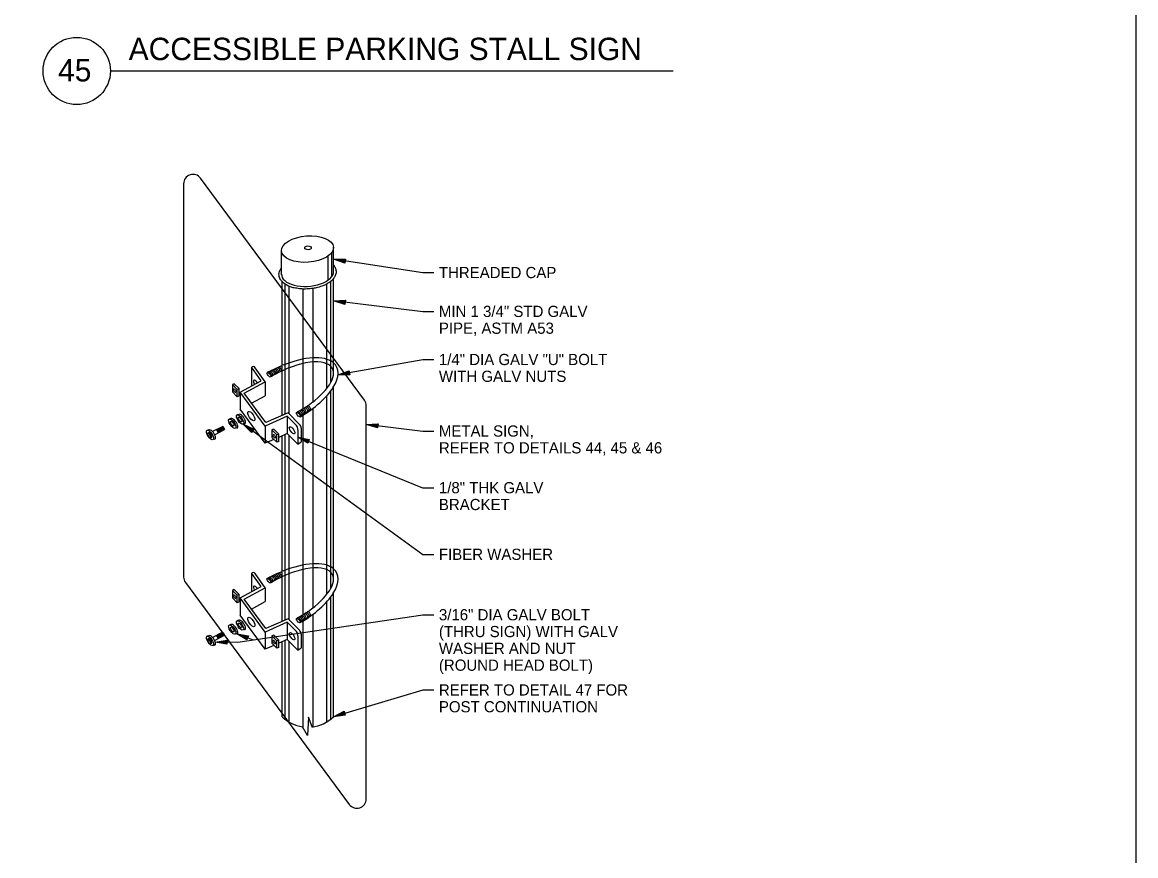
# Model space of a CAD drawing. Extents: x -121933 to -117742, y -103160 to -100084.
# Drawn here: x -118338 to -117742, y -102023 to -101577 of the extents above; entities that cross this region are included whole.
import ezdxf

# ---------------------------------------------------------------- set-up
doc = ezdxf.new("R2010")
doc.units = 0
for name, color, linetype in [('22', 7, 'Continuous'), ('Default', 7, 'Continuous'), ('Misc CnstDet(22)', 7, 'Continuous')]:
    doc.layers.add(name, color=color, linetype=linetype)

msp = doc.modelspace()

# ---------------------------------------------------------------- linework, layer by layer
at = {"layer": '22'}
for p, q in [((-118155.15, -101778.96), (-118242.85, -101660.14)), ((-118251.87, -101663.11), (-118251.87, -101873.69)), ((-118199.46, -101712), (-118199.46, -101699.13)), ((-118174.47, -101714.69), (-118174.47, -101701.82)), ((-118172.49, -101712.73), (-118172.49, -101699.86)), ((-118171.67, -101710.02), (-118171.67, -101697.15)), ((-118171.67, -101764.89), (-118171.67, -101713.91)), ((-118199.06, -101787.14), (-118199.06, -101715.7)), ((-118197.58, -101786.48), (-118197.58, -101716.9)), ((-118195.43, -101786.35), (-118195.43, -101718.01)), ((-118187.84, -101783.21), (-118187.84, -101719.48)), ((-118182.56, -101779.84), (-118182.56, -101719.15)), ((-118175.3, -101772.81), (-118175.3, -101716.82)), ((-118173.15, -101769.59), (-118173.15, -101715.4)), ((-118215.55, -101761.57), (-118215.55, -101771.42)), ((-118208.2, -101769.16), (-118213.52, -101761.62)), ((-118203.53, -101762.51), (-118207.22, -101764.25)), ((-118224.78, -101770.2), (-118225.76, -101770.62)), ((-118223.13, -101773.25), (-118225.76, -101770.62)), ((-118225.76, -101770.62), (-118225.76, -101774.52)), ((-118222.14, -101772.83), (-118224.78, -101770.2)), ((-118222.14, -101772.83), (-118223.13, -101773.25)), ((-118223.13, -101777.21), (-118223.13, -101773.25)), ((-118222.14, -101776.78), (-118222.14, -101772.83)), ((-118219.5, -101775.23), (-118208.2, -101769.16)), ((-118208.2, -101769.16), (-118208.2, -101776.64)), ((-118173.15, -101879.94), (-118173.15, -101774.11)), ((-118171.67, -101873.59), (-118171.67, -101771.91)), ((-118225.76, -101774.57), (-118223.13, -101777.21)), ((-118222.14, -101776.78), (-118223.13, -101777.21)), ((-118221.62, -101774.66), (-118221.62, -101783.89)), ((-118207.82, -101791.05), (-118219.5, -101775.23)), ((-118175.3, -101883.05), (-118175.3, -101776.72)), ((-118196, -101785.78), (-118207.82, -101791.05)), ((-118189.79, -101791.99), (-118196, -101785.78)), ((-118182.56, -101889.82), (-118182.56, -101783.71)), ((-118154.17, -101992.5), (-118154.17, -101781.93)), ((-118226.52, -101788.88), (-118227.56, -101789.17)), ((-118222.33, -101786.62), (-118223.37, -101786.91)), ((-118218.94, -101791.52), (-118219.98, -101791.81)), ((-118196.48, -101787.66), (-118196.48, -101796.89)), ((-118187.84, -101893.81), (-118187.84, -101787.34)), ((-118238.39, -101794.92), (-118239.42, -101795.2)), ((-118238.91, -101796.66), (-118238.43, -101796.38)), ((-118238.15, -101797.08), (-118237.68, -101796.8)), ((-118237.35, -101798.26), (-118236.88, -101797.97)), ((-118231.28, -101793.22), (-118236.41, -101795.76)), ((-118230.24, -101794.83), (-118235.23, -101797.51)), ((-118232.97, -101796.28), (-118234.29, -101794.68)), ((-118234.29, -101794.68), (-118233.3, -101796.47)), ((-118232.69, -101796.14), (-118233.96, -101794.54)), ((-118233.96, -101794.54), (-118232.97, -101796.28)), ((-118232.36, -101795.95), (-118233.58, -101794.35)), ((-118233.58, -101794.35), (-118232.69, -101796.14)), ((-118232.03, -101795.81), (-118233.26, -101794.26)), ((-118233.26, -101794.26), (-118232.36, -101795.95)), ((-118231.75, -101795.62), (-118232.97, -101794.12)), ((-118232.97, -101794.12), (-118232.03, -101795.81)), ((-118231.42, -101795.43), (-118232.74, -101793.98)), ((-118232.74, -101793.98), (-118231.75, -101795.62)), ((-118231.04, -101795.25), (-118232.41, -101793.79)), ((-118232.41, -101793.79), (-118231.42, -101795.43)), ((-118230.66, -101795.06), (-118232.03, -101793.64)), ((-118232.03, -101793.64), (-118231.04, -101795.25)), ((-118230.33, -101794.92), (-118231.7, -101793.5)), ((-118231.7, -101793.5), (-118230.66, -101795.06)), ((-118230.05, -101794.68), (-118231.42, -101793.31)), ((-118231.42, -101793.31), (-118230.33, -101794.92)), ((-118230.05, -101794.3), (-118231.14, -101793.13)), ((-118231.14, -101793.13), (-118230.05, -101794.68)), ((-118230, -101794.3), (-118230.66, -101793.27)), ((-118223.13, -101793.79), (-118224.17, -101794.07)), ((-118208.15, -101792.89), (-118208.15, -101802.12)), ((-118203.64, -101794.54), (-118204.63, -101794.97)), ((-118201.98, -101797.6), (-118204.63, -101794.97)), ((-118204.63, -101794.97), (-118204.63, -101798.87)), ((-118200.99, -101797.18), (-118203.64, -101794.54)), ((-118200.99, -101797.18), (-118201.98, -101797.6)), ((-118201.98, -101801.55), (-118201.98, -101797.6)), ((-118200.99, -101801.13), (-118200.99, -101797.18)), ((-118199.06, -101897.33), (-118199.06, -101798)), ((-118197.58, -101896.72), (-118197.58, -101797.59)), ((-118195.43, -101896.59), (-118195.43, -101797.88)), ((-118190.83, -101794.97), (-118190.83, -101802.54)), ((-118189.03, -101793.98), (-118189.03, -101801.32)), ((-118237.3, -101799.11), (-118236.84, -101798.83)), ((-118234.99, -101799.82), (-118236.03, -101800.1)), ((-118204.63, -101798.92), (-118201.98, -101801.55)), ((-118200.99, -101801.13), (-118201.98, -101801.55)), ((-118190.83, -101802.54), (-118189.03, -101801.32)), ((-118215.55, -101871.81), (-118215.55, -101881.66)), ((-118208.2, -101879.4), (-118213.52, -101871.86)), ((-118203.53, -101872.75), (-118207.22, -101874.49)), ((-118250.89, -101876.66), (-118163.2, -101995.47)), ((-118224.78, -101880.44), (-118225.76, -101880.86)), ((-118223.13, -101883.49), (-118225.76, -101880.86)), ((-118225.76, -101880.86), (-118225.76, -101884.76)), ((-118222.14, -101883.07), (-118224.78, -101880.44)), ((-118219.5, -101885.47), (-118208.2, -101879.4)), ((-118208.2, -101879.4), (-118208.2, -101886.88)), ((-118225.76, -101884.81), (-118223.13, -101887.44)), ((-118222.14, -101883.07), (-118223.13, -101883.49)), ((-118223.13, -101887.44), (-118223.13, -101883.49)), ((-118222.14, -101887.02), (-118223.13, -101887.44)), ((-118222.14, -101887.02), (-118222.14, -101883.07)), ((-118221.62, -101884.9), (-118221.62, -101894.13)), ((-118207.82, -101901.29), (-118219.5, -101885.47)), ((-118175.3, -101951.31), (-118175.3, -101886.96)), ((-118173.15, -101949.81), (-118173.15, -101884.35)), ((-118171.67, -101948.49), (-118171.67, -101882.15)), ((-118226.52, -101899.12), (-118227.56, -101899.41)), ((-118222.33, -101896.86), (-118223.37, -101897.15)), ((-118196, -101896.02), (-118207.82, -101901.29)), ((-118196.48, -101897.9), (-118196.48, -101907.13)), ((-118189.79, -101902.23), (-118196, -101896.02)), ((-118187.84, -101954.62), (-118187.84, -101897.08)), ((-118182.56, -101953.9), (-118182.56, -101893.53)), ((-118238.39, -101905.16), (-118239.42, -101905.44)), ((-118231.28, -101903.46), (-118236.41, -101906)), ((-118230.24, -101905.07), (-118235.23, -101907.75)), ((-118232.97, -101906.52), (-118234.29, -101904.92)), ((-118234.29, -101904.92), (-118233.3, -101906.71)), ((-118232.69, -101906.38), (-118233.96, -101904.78)), ((-118233.96, -101904.78), (-118232.97, -101906.52)), ((-118232.36, -101906.19), (-118233.58, -101904.59)), ((-118233.58, -101904.59), (-118232.69, -101906.38)), ((-118232.03, -101906.05), (-118233.26, -101904.5)), ((-118233.26, -101904.5), (-118232.36, -101906.19)), ((-118231.75, -101905.86), (-118232.97, -101904.36)), ((-118232.97, -101904.36), (-118232.03, -101906.05)), ((-118231.42, -101905.67), (-118232.74, -101904.22)), ((-118232.74, -101904.22), (-118231.75, -101905.86)), ((-118231.04, -101905.49), (-118232.41, -101904.03)), ((-118232.41, -101904.03), (-118231.42, -101905.67)), ((-118230.66, -101905.3), (-118232.03, -101903.88)), ((-118232.03, -101903.88), (-118231.04, -101905.49)), ((-118230.33, -101905.16), (-118231.7, -101903.74)), ((-118231.7, -101903.74), (-118230.66, -101905.3)), ((-118230.05, -101904.92), (-118231.42, -101903.55)), ((-118231.42, -101903.55), (-118230.33, -101905.16)), ((-118230.05, -101904.54), (-118231.14, -101903.37)), ((-118231.14, -101903.37), (-118230.05, -101904.92)), ((-118230, -101904.54), (-118230.66, -101903.51)), ((-118223.13, -101904.03), (-118224.17, -101904.31)), ((-118218.94, -101901.76), (-118219.98, -101902.05)), ((-118208.15, -101903.13), (-118208.15, -101912.36)), ((-118203.64, -101904.78), (-118204.63, -101905.21)), ((-118201.98, -101907.84), (-118204.63, -101905.21)), ((-118204.63, -101905.21), (-118204.63, -101909.11)), ((-118200.99, -101907.42), (-118203.64, -101904.78)), ((-118190.83, -101905.21), (-118190.83, -101912.78)), ((-118189.03, -101904.22), (-118189.03, -101911.56)), ((-118238.91, -101906.9), (-118238.43, -101906.62)), ((-118238.15, -101907.32), (-118237.68, -101907.04)), ((-118237.35, -101908.5), (-118236.88, -101908.21)), ((-118237.3, -101909.35), (-118236.84, -101909.07)), ((-118234.99, -101910.06), (-118236.03, -101910.34)), ((-118204.63, -101909.16), (-118201.98, -101911.79)), ((-118200.99, -101907.42), (-118201.98, -101907.84)), ((-118201.98, -101911.79), (-118201.98, -101907.84)), ((-118200.99, -101911.37), (-118201.98, -101911.79)), ((-118200.99, -101911.37), (-118200.99, -101907.42)), ((-118199.06, -101948.49), (-118199.06, -101908.29)), ((-118197.58, -101949.81), (-118197.58, -101907.63)), ((-118195.43, -101951.31), (-118195.43, -101908.18)), ((-118190.83, -101912.78), (-118189.03, -101911.56)), ((-118185.1, -101948.65), (-118185.6, -101958.56)), ((-118183.14, -101953.98), (-118185.1, -101948.65)), ((-118185.6, -101958.56), (-118188.26, -101953.89))]:
    msp.add_line(p, q, dxfattribs=at)
for points in [[(-118165.32, -101703.45), (-118165.66, -101705.62), (-118171.67, -101703.58), (-118165.32, -101703.45), (-118165.78, -101704.49), (-118165.81, -101705.29), (-118170.32, -101703.74), (-118165.55, -101703.61), (-118165.98, -101704.46), (-118166.06, -101704.95), (-118169.19, -101703.91), (-118165.99, -101703.85), (-118166.18, -101704.78), (-118168.06, -101704.14), (-118166.23, -101704.12), (-118166.45, -101704.54), (-118167.07, -101704.29), (-118165.49, -101704.53)], [(-118117.93, -101710.9), (-118123.93, -101710.9), (-118171.67, -101703.58)], [(-118165.33, -101725.56), (-118165.59, -101727.75), (-118171.67, -101725.9), (-118165.33, -101725.56), (-118165.76, -101726.62), (-118165.76, -101727.43), (-118170.32, -101726.02), (-118165.55, -101725.74), (-118165.96, -101726.6), (-118166.02, -101727.09), (-118169.18, -101726.15), (-118165.98, -101725.99), (-118166.15, -101726.93), (-118168.04, -101726.34), (-118166.22, -101726.26), (-118166.42, -101726.69), (-118167.05, -101726.46), (-118165.46, -101726.66)], [(-118117.93, -101731.69), (-118123.93, -101731.69), (-118171.67, -101725.9)], [(-118191.53, -101792.61), (-118196.48, -101787.66), (-118208.15, -101792.89), (-118221.62, -101774.66), (-118210.32, -101768.59), (-118215.31, -101761.57)], [(-118117.93, -101757.44), (-118123.93, -101757.44), (-118169.26, -101765.52)], [(-118163.29, -101763.35), (-118162.91, -101765.52), (-118169.26, -101765.52), (-118163.29, -101763.35), (-118163.4, -101764.48), (-118163.16, -101765.26), (-118167.94, -101765.23), (-118163.46, -101763.58), (-118163.6, -101764.52), (-118163.51, -101765.01), (-118166.81, -101765.03), (-118163.8, -101763.95), (-118163.68, -101764.89), (-118165.66, -101764.88), (-118163.94, -101764.28), (-118164.01, -101764.75), (-118164.68, -101764.71), (-118163.1, -101764.43)], [(-118215.5, -101780.65), (-118208.2, -101776.64)], [(-118203.53, -101800.05), (-118208.15, -101802.12), (-118221.62, -101783.89)], [(-118117.93, -101861.74), (-118123.93, -101861.74), (-118219.98, -101791.81)], [(-118214.27, -101794.58), (-118215.56, -101796.36), (-118219.98, -101791.81), (-118214.27, -101794.58), (-118215.16, -101795.29), (-118215.55, -101796), (-118218.86, -101792.56), (-118214.55, -101794.62), (-118215.32, -101795.17), (-118215.62, -101795.58), (-118217.93, -101793.23), (-118215.05, -101794.63), (-118215.65, -101795.37), (-118217.03, -101793.94), (-118215.39, -101794.76), (-118215.78, -101795.03), (-118216.22, -101794.53), (-118214.92, -101795.47)], [(-118147.84, -101791.72), (-118148.1, -101793.9), (-118154.17, -101792.06), (-118147.84, -101791.72), (-118148.26, -101792.77), (-118148.26, -101793.58), (-118152.83, -101792.17), (-118148.06, -101791.89), (-118148.46, -101792.75), (-118148.52, -101793.25), (-118151.68, -101792.31), (-118148.49, -101792.14), (-118148.65, -101793.08), (-118150.55, -101792.5), (-118148.73, -101792.42), (-118148.93, -101792.84), (-118149.56, -101792.62), (-118147.97, -101792.81)], [(-118117.93, -101795.73), (-118123.93, -101795.73), (-118154.17, -101792.06)], [(-118237.59, -101797.83), (-118238.15, -101797.08), (-118238.91, -101796.66), (-118239.19, -101797.12), (-118238.81, -101798.02), (-118238.34, -101798.64), (-118237.83, -101799.11), (-118237.3, -101799.11), (-118237.35, -101798.26), (-118237.63, -101797.79)], [(-118237.12, -101797.55), (-118237.68, -101796.8), (-118238.43, -101796.38), (-118238.43, -101796.42)], [(-118236.88, -101798.83), (-118236.84, -101798.83), (-118236.88, -101797.97), (-118237.16, -101797.51)], [(-118190.83, -101802.54), (-118196.48, -101796.89), (-118200.99, -101798.92)], [(-118117.93, -101826.09), (-118123.93, -101826.09), (-118190.83, -101798.75)], [(-118184.62, -101800.08), (-118185.44, -101802.12), (-118190.83, -101798.75), (-118184.62, -101800.08), (-118185.31, -101800.98), (-118185.52, -101801.76), (-118189.56, -101799.21), (-118184.88, -101800.19), (-118185.5, -101800.91), (-118185.68, -101801.37), (-118188.49, -101799.64), (-118185.36, -101800.32), (-118185.77, -101801.18), (-118187.44, -101800.12), (-118185.66, -101800.52), (-118185.97, -101800.88), (-118186.52, -101800.5), (-118185.03, -101801.1)], [(-118191.53, -101902.85), (-118196.48, -101897.9), (-118208.15, -101903.13), (-118221.62, -101884.9), (-118210.32, -101878.83), (-118215.31, -101871.81)], [(-118215.5, -101890.89), (-118208.2, -101886.88)], [(-118117.93, -101894.09), (-118123.93, -101894.09), (-118222.94, -101908.66)], [(-118203.53, -101910.29), (-118208.15, -101912.36), (-118221.62, -101894.13)], [(-118214.56, -101907.42), (-118223.44, -101904.11)], [(-118217.2, -101905.24), (-118217.96, -101907.31), (-118223.44, -101904.11), (-118217.2, -101905.24), (-118217.86, -101906.17), (-118218.04, -101906.96), (-118222.16, -101904.53), (-118217.45, -101905.36), (-118218.04, -101906.1), (-118218.22, -101906.57), (-118221.08, -101904.93), (-118217.93, -101905.5), (-118218.31, -101906.38), (-118220.01, -101905.38), (-118218.22, -101905.72), (-118218.52, -101906.09), (-118219.08, -101905.72), (-118217.58, -101906.27)], [(-118237.59, -101908.07), (-118238.15, -101907.32), (-118238.91, -101906.9), (-118239.19, -101907.36), (-118238.81, -101908.26), (-118238.34, -101908.88), (-118237.83, -101909.35), (-118237.3, -101909.35), (-118237.35, -101908.5), (-118237.63, -101908.03)], [(-118237.12, -101907.79), (-118237.68, -101907.04), (-118238.43, -101906.62), (-118238.43, -101906.66)], [(-118236.88, -101909.07), (-118236.84, -101909.07), (-118236.88, -101908.21), (-118237.16, -101907.75)], [(-118228.64, -101907.48), (-118228.66, -101909.68), (-118234.9, -101908.52), (-118228.64, -101907.48), (-118228.95, -101908.58), (-118228.86, -101909.38), (-118233.55, -101908.48), (-118228.84, -101907.68), (-118229.15, -101908.57), (-118229.16, -101909.07), (-118232.4, -101908.49), (-118229.25, -101907.98), (-118229.31, -101908.92), (-118231.25, -101908.55), (-118229.45, -101908.27), (-118229.6, -101908.72), (-118230.25, -101908.56), (-118228.65, -101908.58)], [(-118222.94, -101908.66), (-118234.9, -101908.52)], [(-118190.83, -101912.78), (-118196.48, -101907.13), (-118200.99, -101909.16)], [(-118117.93, -101934.35), (-118123.93, -101934.35), (-118171.67, -101948.49)], [(-118166.02, -101945.59), (-118165.37, -101947.69), (-118171.67, -101948.49), (-118166.02, -101945.59), (-118165.98, -101946.72), (-118165.65, -101947.46), (-118170.39, -101948.04), (-118166.16, -101945.84), (-118166.17, -101946.78), (-118166.03, -101947.26), (-118169.29, -101947.7), (-118166.45, -101946.24), (-118166.21, -101947.16), (-118168.18, -101947.41), (-118166.55, -101946.59), (-118166.56, -101947.06), (-118167.23, -101947.11), (-118165.7, -101946.64)]]:
    msp.add_lwpolyline(points, dxfattribs=at)
for centre, radius, start, end in [((-118246.87, -101663.11), 5, 36.43174, 180), ((-118214.55, -101762.24), 1.2, 30.9874, 146.34816), ((-118215.4, -101761.74), 0.217, 77.47119, 130.60129), ((-118203.76, -101764.36), 1.98, 353.31833, 77.99232), ((-118203, -101763.94), 1.98, 353.31833, 77.99232), ((-118202.25, -101763.61), 1.98, 353.31833, 77.99232), ((-118201.54, -101763.28), 1.98, 353.31833, 77.99232), ((-118206.78, -101765.9), 1.92, 348.22852, 85.91464), ((-118206.03, -101765.52), 1.92, 348.22852, 85.91464), ((-118205.18, -101765.1), 1.92, 348.22852, 85.91464), ((-118204.51, -101764.74), 1.98, 353.31833, 77.99232), ((-118159.17, -101781.93), 5, 0, 36.43174), ((-118191, -101787.23), 1.92, 348.22852, 85.91464), ((-118190.3, -101786.81), 1.92, 348.22852, 85.91464), ((-118189.59, -101786.38), 1.92, 348.22852, 85.91464), ((-118188.93, -101785.96), 1.92, 348.22852, 85.91464), ((-118188.13, -101785.53), 1.92, 348.22852, 85.91464), ((-118187.33, -101784.97), 1.92, 348.22852, 85.91464), ((-118186.58, -101784.45), 1.92, 348.22852, 85.91464), ((-118185.82, -101783.98), 1.92, 348.22852, 85.91464), ((-118191.6, -101793.83), 2.58, 356.62671, 44.91779), ((-118231.01, -101793.68), 0.549, 50.75624, 120.41569), ((-118230.38, -101794.45), 0.402, 290.55604, 20.55604), ((-118193.35, -101794.44), 2.58, 348.5235, 44.9178), ((-118246.87, -101873.69), 5, 180, 216.43174), ((-118214.55, -101872.48), 1.2, 30.9874, 146.34816), ((-118215.4, -101871.98), 0.217, 77.47119, 130.60129), ((-118206.78, -101876.14), 1.92, 348.22852, 85.91464), ((-118206.03, -101875.76), 1.92, 348.22852, 85.91464), ((-118205.18, -101875.34), 1.92, 348.22852, 85.91464), ((-118204.51, -101874.98), 1.98, 353.31833, 77.99232), ((-118203.76, -101874.6), 1.98, 353.31833, 77.99232), ((-118203, -101874.18), 1.98, 353.31833, 77.99232), ((-118202.25, -101873.85), 1.98, 353.31833, 77.99232), ((-118201.54, -101873.52), 1.98, 353.31833, 77.99232), ((-118187.33, -101895.21), 1.92, 348.22852, 85.91464), ((-118186.58, -101894.69), 1.92, 348.22852, 85.91464), ((-118185.82, -101894.22), 1.92, 348.22852, 85.91464), ((-118191, -101897.47), 1.92, 348.22852, 85.91464), ((-118190.3, -101897.04), 1.92, 348.22852, 85.91464), ((-118189.59, -101896.62), 1.92, 348.22852, 85.91464), ((-118188.93, -101896.2), 1.92, 348.22852, 85.91464), ((-118188.13, -101895.77), 1.92, 348.22852, 85.91464), ((-118231.01, -101903.92), 0.549, 50.75624, 120.41569), ((-118230.38, -101904.69), 0.402, 290.55604, 20.55604), ((-118193.35, -101904.68), 2.58, 348.5235, 44.9178), ((-118191.6, -101904.07), 2.58, 356.62671, 44.91779), ((-118185.36, -101934.58), 19.52, 225.43812, 261.69071), ((-118185.36, -101934.58), 19.52, 276.12211, 314.56188), ((-118159.17, -101992.5), 5, 216.43174, 0)]:
    msp.add_arc(centre, radius, start, end, dxfattribs=at)
for centre, major_axis, ratio in [((-118185.56, -101698.14), (-13.9, -0.99), 0.50721), ((-118185.31, -101697.46), (-1.77, -0.06), 0.577116), ((-118206.24, -101765.42), (-0.97, 1.15), 0.383233), ((-118206.24, -101765.42), (-0.97, 1.15), 0.383233), ((-118224.49, -101773.96), (0.646, -0.94), 0.40079), ((-118215.64, -101787.53), (1.68, -2.44), 0.40079), ((-118190.47, -101786.75), (-0.97, 1.15), 0.383233), ((-118225.86, -101791.62), (1.68, -2.44), 0.40079), ((-118225.86, -101791.62), (0.84, -1.22), 0.40079), ((-118221.66, -101789.36), (1.68, -2.44), 0.40079), ((-118221.66, -101789.36), (0.84, -1.22), 0.40079), ((-118237.72, -101797.65), (1.68, -2.44), 0.40079), ((-118203.35, -101798.31), (0.646, -0.94), 0.40079), ((-118193.83, -101795.15), (1.29, -1.88), 0.40079), ((-118206.24, -101875.66), (-0.97, 1.15), 0.383233), ((-118206.24, -101875.66), (-0.97, 1.15), 0.383233), ((-118224.49, -101884.2), (0.646, -0.94), 0.40079), ((-118225.86, -101901.86), (1.68, -2.44), 0.40079), ((-118221.66, -101899.6), (1.68, -2.44), 0.40079), ((-118221.66, -101899.6), (0.84, -1.22), 0.40079), ((-118215.64, -101897.77), (1.68, -2.44), 0.40079), ((-118190.47, -101896.99), (-0.97, 1.15), 0.383233), ((-118237.72, -101907.89), (1.68, -2.44), 0.40079), ((-118225.86, -101901.86), (0.84, -1.22), 0.40079), ((-118193.83, -101905.39), (1.29, -1.88), 0.40079), ((-118203.35, -101908.55), (0.646, -0.94), 0.40079)]:
    msp.add_ellipse(centre, major_axis=major_axis, ratio=ratio, dxfattribs=at)
for centre, major_axis, ratio, start_param, end_param in [((-118185.56, -101711.01), (-13.9, -0.99), 0.50721, 6.210939, 9.409079), ((-118198.19, -101776.11), (-28.17, -15.1), 0.453878, 3.333026, 4.493389), ((-118198.19, -101776.11), (-28.17, -15.1), 0.453878, 4.503849, 4.659634), ((-118196.92, -101775.26), (-24.64, -13.25), 0.417549, 2.948396, 4.572315), ((-118198.19, -101776.11), (-28.17, -15.1), 0.453878, 1.635731, 3.31856), ((-118213.09, -101770.2), (1.29, -1.88), 0.40079, 1.582571, 4.626709), ((-118196.92, -101775.26), (-24.64, -13.25), 0.417549, 4.576463, 4.828697), ((-118196.92, -101775.26), (-24.64, -13.25), 0.417549, 1.568045, 2.928691), ((-118224.82, -101791.34), (1.68, -2.44), 0.40079, 6.029102, 9.372684), ((-118220.63, -101789.08), (1.68, -2.44), 0.40079, 6.029102, 9.372684), ((-118236.69, -101797.37), (1.68, -2.44), 0.40079, 6.029102, 9.372684), ((-118196.92, -101885.5), (-24.64, -13.25), 0.417549, 2.948396, 4.572315), ((-118198.19, -101886.35), (-28.17, -15.1), 0.453878, 3.333026, 4.493389), ((-118198.19, -101886.35), (-28.17, -15.1), 0.453878, 1.635731, 3.31856), ((-118196.92, -101885.5), (-24.64, -13.25), 0.417549, 4.576463, 4.828697), ((-118198.19, -101886.35), (-28.17, -15.1), 0.453878, 4.503849, 4.659634), ((-118196.92, -101885.5), (-24.64, -13.25), 0.417549, 1.568045, 2.928691), ((-118213.09, -101880.44), (1.29, -1.88), 0.40079, 1.582571, 4.626709), ((-118224.82, -101901.58), (1.68, -2.44), 0.40079, 6.029102, 9.372684), ((-118220.63, -101899.32), (1.68, -2.44), 0.40079, 6.029102, 9.372684), ((-118236.69, -101907.61), (1.68, -2.44), 0.40079, 6.029102, 9.372684)]:
    msp.add_ellipse(centre, major_axis=major_axis, ratio=ratio, start_param=start_param, end_param=end_param, dxfattribs=at)
for points in [[(-118200.82, -101712.1), (-118200.87, -101711.45), (-118200.78, -101710.8), (-118200.4, -101709.57), (-118200.1, -101708.99), (-118199.63, -101708.33), (-118199.55, -101708.22), (-118199.46, -101708.1)], [(-118171.67, -101706.75), (-118171.32, -101707.16), (-118171.03, -101707.6), (-118170.52, -101708.65), (-118170.35, -101709.28), (-118170.26, -101710.57), (-118170.34, -101711.21), (-118170.73, -101712.44), (-118171.03, -101713.03), (-118171.8, -101714.13), (-118172.27, -101714.64), (-118173.37, -101715.6), (-118173.99, -101716.05), (-118176.06, -101717.29), (-118177.66, -101717.96), (-118181.15, -101718.95), (-118183.03, -101719.28), (-118186.9, -101719.56), (-118188.81, -101719.5), (-118192.4, -101719.01), (-118194.08, -101718.58), (-118196.31, -101717.64), (-118196.98, -101717.28), (-118198.2, -101716.49), (-118198.74, -101716.05), (-118199.66, -101715.07), (-118200.05, -101714.53), (-118200.6, -101713.37), (-118200.78, -101712.74), (-118200.82, -101712.1)]]:
    msp.add_open_spline(points, degree=3, dxfattribs=at)
at = {"layer": 'Default'}
msp.add_lwpolyline([(-119542.38, -101122.36), (-117742.38, -101122.36), (-117742.38, -102572.36), (-119542.38, -102572.36)], close=True, dxfattribs=at)
at = {"layer": 'Misc CnstDet(22)'}
msp.add_line((-118291.07, -101602.77), (-117989.85, -101602.77), dxfattribs=at)
msp.add_circle((-118309.07, -101602.77), 18, dxfattribs=at)

# ---------------------------------------------------------------- texts
at = {"layer": '22'}
for s, p in [('THREADED CAP', (-118115.26, -101713.69)), ('MIN 1 3/4" STD GALV', (-118115.26, -101734.48)), ('PIPE, ASTM A53', (-118115.26, -101743.48)), ('1/4" DIA GALV "U" BOLT', (-118115.26, -101760.23)), ('WITH GALV NUTS', (-118115.26, -101769.23)), ('METAL SIGN,', (-118115.26, -101798.52)), ('REFER TO DETAILS 44, 45 & 46', (-118115.26, -101807.52)), ('1/8" THK GALV', (-118115.26, -101828.88)), ('BRACKET', (-118115.26, -101837.88)), ('FIBER WASHER', (-118115.26, -101864.53)), ('3/16" DIA GALV BOLT', (-118115.26, -101896.88)), ('(THRU SIGN) WITH GALV', (-118115.26, -101905.88)), ('WASHER AND NUT', (-118115.26, -101914.88)), ('(ROUND HEAD BOLT)', (-118115.26, -101923.88)), ('REFER TO DETAIL 47 FOR', (-118115.26, -101937.14)), ('POST CONTINUATION', (-118115.26, -101946.14))]:
    msp.add_text(s, height=6, dxfattribs=at).set_placement(p)
at = {"layer": 'Misc CnstDet(22)'}
for s, p in [('ACCESSIBLE PARKING STALL SIGN', (-118281.28, -101596.97)), ('45', (-118319.06, -101608.38))]:
    msp.add_text(s, height=12, dxfattribs=at).set_placement(p)

doc.saveas('drawing.dxf')
